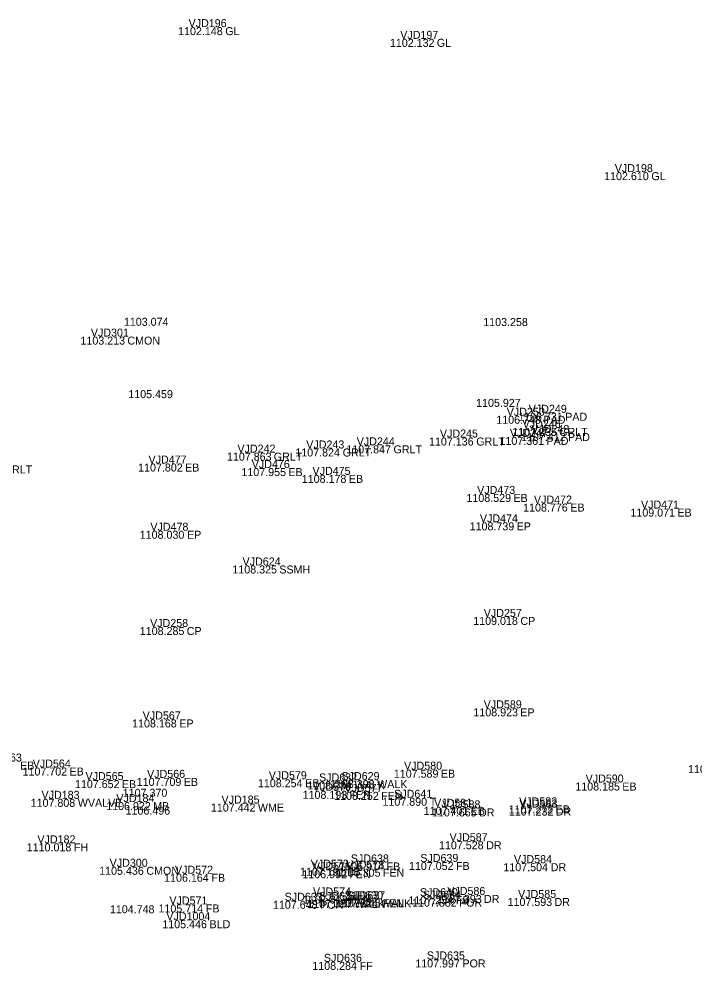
# Model space of a CAD drawing. Extents: x 1629927 to 1630657, y 484405 to 484576.
# Drawn here: x 1630340.9 to 1630425.4, y 484449.5 to 484568.4 of the extents above; entities that cross this region are included whole.
import ezdxf

# ---------------------------------------------------------------- set-up
doc = ezdxf.new("R2010")
doc.units = 0
for name, color, linetype in [('SV_X_Text_Comment', 7, 'Continuous'), ('SV_X_Text_Elevation', 7, 'Continuous'), ('SV_X_Text_Name', 7, 'Continuous')]:
    doc.layers.add(name, color=color, linetype=linetype)

msp = doc.modelspace()

# ---------------------------------------------------------------- texts
at = {"layer": 'SV_X_Text_Comment'}
for s, p in [('GL', (1630366.66, 484566.36)), ('GL', (1630393.12, 484564.9)), ('GL', (1630419.95, 484548.24)), ('CMON', (1630354.42, 484527.69)), ('PAD', (1630406.45, 484517.8)), ('PAD', (1630409.17, 484518.17)), ('GRLT', (1630408.42, 484516.28)), ('GRLT', (1630398.05, 484515.08)), ('PAD', (1630406.83, 484515.16)), ('PAD', (1630409.52, 484515.64)), ('GRLT', (1630381.34, 484513.71)), ('GRLT', (1630387.7, 484514.1)), ('GRLT', (1630372.73, 484513.19)), ('GRLT', (1630338.95, 484511.59)), ('EB', (1630361.64, 484511.83)), ('EB', (1630374.55, 484511.26)), ('EB', (1630382.12, 484510.41)), ('EB', (1630402.7, 484508.03)), ('EB', (1630409.81, 484506.83)), ('EB', (1630423.21, 484506.2)), ('EP', (1630403.1, 484504.48)), ('EP', (1630361.88, 484503.43)), ('SSMH', (1630373.42, 484499.09)), ('CP', (1630403.57, 484492.66)), ('CP', (1630361.84, 484491.4)), ('EP', (1630403.55, 484481.24)), ('EP', (1630360.91, 484479.85)), ('EB', (1630341, 484474.59)), ('EB', (1630347.18, 484473.84)), ('EB', (1630393.62, 484473.57)), ('EB', (1630353.73, 484472.27)), ('EB', (1630361.47, 484472.55)), ('EB', (1630376.66, 484472.38)), ('WALK', (1630382.84, 484472.11)), ('WALK', (1630385.65, 484472.27)), ('FEN', (1630382.19, 484470.93)), ('EB', (1630416.31, 484471.97)), ('WVALVE', (1630348.22, 484469.93)), ('FEN', (1630386.15, 484470.8)), ('T', (1630392.23, 484470.06)), ('MB', (1630357.64, 484469.52)), ('WME', (1630370.74, 484469.34)), ('EB', (1630397.35, 484468.93)), ('DR', (1630398.39, 484468.73)), ('EB', (1630407.97, 484469.11)), ('DR', (1630407.99, 484468.84)), ('FH', (1630347.73, 484464.37)), ('DR', (1630399.29, 484464.63)), ('CMON', (1630356.79, 484461.44)), ('FB', (1630386.83, 484461.98)), ('FB', (1630395.51, 484462.04)), ('DR', (1630407.36, 484461.89)), ('FB', (1630364.93, 484460.57)), ('FB', (1630381.89, 484461.32)), ('FEN', (1630382.17, 484461.01)), ('FEN', (1630386.37, 484461.2)), ('FEN', (1630382.23, 484457.85)), ('DR', (1630399.01, 484457.92)), ('FB', (1630364.23, 484456.73)), ('POR', (1630378.52, 484457.19)), ('WALK', (1630382.82, 484457.29)), ('WALK', (1630386.12, 484457.39)), ('FEN', (1630386.36, 484457.38)), ('FB', (1630395.49, 484457.76)), ('POR', (1630395.89, 484457.46)), ('DR', (1630407.83, 484457.54)), ('BLD', (1630364.69, 484454.76)), ('FF', (1630383.47, 484449.56)), ('POR', (1630396.32, 484449.86))]:
    msp.add_text(s, height=1, dxfattribs=at).set_placement(p)
at = {"layer": 'SV_X_Text_Elevation'}
for s, p in [('1102.148', (1630360.76, 484566.36)), ('1102.132', (1630387.25, 484564.9)), ('1102.610', (1630414.04, 484548.24)), ('1103.074', (1630353.98, 484530.04)), ('1103.258', (1630398.92, 484530.01)), ('1103.213', (1630348.55, 484527.69)), ('1105.459', (1630354.53, 484521)), ('1105.927', (1630398.03, 484519.91)), ('1106.748', (1630400.55, 484517.8)), ('1106.731', (1630403.29, 484518.17)), ('1107.235', (1630402.55, 484516.28)), ('1107.136', (1630392.14, 484515.08)), ('1107.361', (1630400.95, 484515.16)), ('1107.412', (1630403.65, 484515.64)), ('1107.824', (1630375.42, 484513.71)), ('1107.847', (1630381.8, 484514.1)), ('1107.863', (1630366.87, 484513.19)), ('1107.802', (1630355.76, 484511.83)), ('1107.955', (1630368.68, 484511.26)), ('1108.178', (1630376.23, 484510.41)), ('1108.529', (1630396.82, 484508.03)), ('1108.776', (1630403.91, 484506.83)), ('1109.071', (1630417.33, 484506.2)), ('1108.739', (1630397.22, 484504.48)), ('1108.030', (1630355.96, 484503.43)), ('1108.325', (1630367.55, 484499.09)), ('1109.018', (1630397.67, 484492.66)), ('1108.285', (1630355.97, 484491.4)), ('1108.923', (1630397.69, 484481.24)), ('1108.168', (1630355.01, 484479.85)), ('1107.702', (1630341.31, 484473.84)), ('1107.589', (1630387.74, 484473.57)), ('1109.036', (1630424.53, 484474.14)), ('1107.652', (1630347.86, 484472.27)), ('1107.709', (1630355.59, 484472.55)), ('1108.254', (1630370.74, 484472.38)), ('1108.284', (1630376.91, 484472.11)), ('1108.398', (1630379.75, 484472.27)), ('1107.370', (1630353.84, 484471.19)), ('1108.193', (1630376.33, 484470.93)), ('1108.185', (1630410.44, 484471.97)), ('1107.808', (1630342.32, 484469.93)), ('1108.252', (1630380.28, 484470.8)), ('1107.890', (1630386.32, 484470.06)), ('1106.922', (1630351.77, 484469.52)), ('1106.496', (1630354.19, 484468.96)), ('1107.442', (1630364.86, 484469.34)), ('1107.401', (1630391.47, 484468.93)), ('1107.665', (1630392.52, 484468.73)), ('1107.272', (1630402.09, 484469.11)), ('1107.232', (1630402.12, 484468.84)), ('1110.018', (1630341.83, 484464.37)), ('1107.528', (1630393.39, 484464.63)), ('1105.436', (1630350.89, 484461.44)), ('1106.914', (1630380.91, 484461.98)), ('1107.052', (1630389.63, 484462.04)), ('1107.504', (1630401.44, 484461.89)), ('1106.164', (1630359.01, 484460.57)), ('1107.191', (1630376.01, 484461.32)), ('1106.992', (1630376.3, 484461.01)), ('1107.305', (1630380.5, 484461.2)), ('1107.813', (1630376.37, 484457.85)), ('1107.393', (1630393.15, 484457.92)), ('1105.714', (1630358.31, 484456.73)), ('1107.648', (1630372.62, 484457.19)), ('1107.777', (1630376.92, 484457.29)), ('1107.824', (1630380.2, 484457.39)), ('1107.445', (1630380.5, 484457.38)), ('1107.254', (1630389.57, 484457.76)), ('1107.882', (1630390.02, 484457.46)), ('1107.593', (1630401.96, 484457.54)), ('1104.748', (1630352.23, 484456.63)), ('1105.446', (1630358.79, 484454.76)), ('1108.284', (1630377.55, 484449.56)), ('1107.997', (1630390.42, 484449.86))]:
    msp.add_text(s, height=1, dxfattribs=at).set_placement(p)
at = {"layer": 'SV_X_Text_Name'}
for s, p in [('VJD196', (1630362.07, 484567.36)), ('VJD197', (1630388.54, 484565.9)), ('VJD198', (1630415.37, 484549.24)), ('VJD301', (1630349.85, 484528.69)), ('VJD250', (1630401.86, 484518.8)), ('VJD249', (1630404.61, 484519.17)), ('VJD246', (1630403.84, 484517.28)), ('VJD245', (1630393.5, 484516.08)), ('VJD247', (1630402.25, 484516.16)), ('VJD248', (1630404.94, 484516.64)), ('VJD244', (1630383.1, 484515.1)), ('VJD242', (1630368.18, 484514.19)), ('VJD243', (1630376.79, 484514.71)), ('VJD477', (1630357.06, 484512.83)), ('VJD476', (1630369.97, 484512.26)), ('VJD475', (1630377.57, 484511.41)), ('VJD473', (1630398.16, 484509.03)), ('VJD472', (1630405.26, 484507.83)), ('VJD471', (1630418.65, 484507.2)), ('VJD474', (1630398.5, 484505.48)), ('VJD478', (1630357.29, 484504.43)), ('VJD624', (1630368.82, 484500.09)), ('VJD257', (1630398.99, 484493.66)), ('VJD258', (1630357.26, 484492.4)), ('VJD589', (1630398.98, 484482.24)), ('VJD567', (1630356.33, 484480.85)), ('VJD563', (1630336.46, 484475.59)), ('VJD564', (1630342.58, 484474.84)), ('VJD580', (1630389.02, 484474.57)), ('VJD566', (1630356.88, 484473.55)), ('VJD579', (1630372.1, 484473.38)), ('VJD565', (1630349.18, 484473.27)), ('SJD632', (1630378.39, 484473.11)), ('SJD629', (1630381.19, 484473.27)), ('VJD590', (1630411.72, 484472.97)), ('VJD183', (1630343.68, 484470.93)), ('VJD576', (1630377.61, 484471.93)), ('VJD577', (1630381.57, 484471.8)), ('SJD641', (1630387.78, 484471.06)), ('VJD184', (1630353.04, 484470.52)), ('VJD185', (1630366.19, 484470.34)), ('VJD581', (1630392.78, 484469.93)), ('VJD588', (1630393.81, 484469.73)), ('VJD582', (1630403.41, 484470.11)), ('VJD583', (1630403.44, 484469.84)), ('VJD182', (1630343.17, 484465.37)), ('VJD587', (1630394.71, 484465.63)), ('SJD638', (1630382.36, 484462.98)), ('SJD639', (1630391.05, 484463.04)), ('VJD584', (1630402.76, 484462.89)), ('VJD300', (1630352.2, 484462.44)), ('VJD572', (1630360.37, 484461.57)), ('VJD573', (1630377.35, 484462.32)), ('VJD575', (1630377.62, 484462.01)), ('VJD578', (1630381.79, 484462.2)), ('SJD633', (1630374.08, 484458.19)), ('VJD574', (1630377.63, 484458.85)), ('SJD631', (1630378.36, 484458.29)), ('SJD630', (1630381.64, 484458.39)), ('SJD637', (1630381.89, 484458.38)), ('SJD640', (1630391, 484458.76)), ('SJD634', (1630391.39, 484458.46)), ('VJD586', (1630394.42, 484458.92)), ('VJD585', (1630403.28, 484458.54)), ('VJD571', (1630359.67, 484457.73)), ('VJD1004', (1630359.29, 484455.76)), ('SJD635', (1630391.87, 484450.86)), ('SJD636', (1630378.99, 484450.56))]:
    msp.add_text(s, height=1, dxfattribs=at).set_placement(p)

doc.saveas('drawing.dxf')
